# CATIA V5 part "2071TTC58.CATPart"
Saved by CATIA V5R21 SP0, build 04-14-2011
Part number: 2071TTC58
Bounding box of the stored display mesh (mm): x -10 to 10, y 0 to 1000, z -19.5 to 16.5
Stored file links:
  C:\Users\ALI OZGUN\Desktop\alhan\PROFILLER\2071TTC58.CATPart
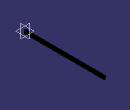
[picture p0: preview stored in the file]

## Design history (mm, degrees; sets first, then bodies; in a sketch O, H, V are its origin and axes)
Body1 (main body)
  Sketch1 on zx-plane, origin (0, 0, 0), H (-1, 0, 0), V (0, 0, 1)
    line L1 (10, 13.9) -> (10, -16.5)
    line L2 (10, -16.5) -> (-10, -16.5)
    line L3 (-10, -16.5) -> (-10, -3.2)
    line L4 (-10, 16.5) -> (-0.8, 16.5)
    point P4 (-10, 2)
    line L5 (-0.8, -3.2) -> (-10, -3.2)
    line L6 (-10, 7.2) -> (-0.8, 7.2)
    point P5 (-9.0936, 12.527)
    point P6 (2, 2)
    line L7 (4.8, 9.75) -> (4.8, -5.75)
    line L8 (4.8, -5.75) -> (-0.8, -5.75)
    line L9 (-0.8, -5.75) -> (-0.8, -3.2)
    line L10 (-0.8, 9.75) -> (4.8, 9.75)
    line L11 (10, 13.9) -> (-0.8, 13.9)
    line L12 (-0.8, 13.9) -> (-0.8, 16.5)
    axis line L13 (-44.5224, 2) -> (23.1973, 2)
    line L14 (-10, 7.2) -> (-10, 16.5)
    point P18 (-0.8, 7.2)
    line L15 (-0.8, 7.2) -> (-0.8, 9.75)
    distance L6 L5 = 10.4
    distance L10 L8 = 15.5
    distance L7 L9 = 5.6
    distance L12 L3 = 9.2
    distance L1 L3 = 20
    distance L4 L2 = 33
    distance L13 L2 = 18.5
    distance L11 L4 = 2.6
    vertical: L1 V, L3 V, L7 V, L9 V, L12 V, L14 V, L15 V
    horizontal: L2 H, L4 H, L5 H, L6 H, L8 H, L10 H, L11 H, L13 H
    equidistance: L1 L3 O, L2 L4 O, L5 L6 P4, L7 L9 P6, L8 L10 P6
    coincidence: P4 L3, L9 L12, L3 L14, L9 P18, L9 L15
    symmetry: L6 L5 L13, L8 L10 L13
  Pad1: profile Sketch1, direction (0, 1, 0), length 1000
  Body2
    Solid1: linked copy from another document
  Remove1: tool Body2
  RemoveFace1: RemoveFaces (face of Solid1; face of Solid1)
Body3
  Sketch2 on start face of Pad1, origin (0, 0, 0), H (1, 0, 0), V (0, 0, 1)
    point P1 (0, -11.1417)
    line L1 (10, -10.5) -> (10, -18.5)
    line L2 (9, -19.5) -> (-9, -19.5)
    line L3 (-10, -18.5) -> (-10, -10.5)
    line L4 (9, -9.5) -> (5, -9.5)
    point P2 (5, -9.5)
    line L5 (-9, -9.5) -> (-5, -9.5)
    point P3 (-5, -9.5)
    reference projected line E1 (0.8, 16.5) -> (10, 16.5) from edge [start face of Pad1 | face of Pad1 from Sketch1.L4]
    arc A1 centre (9, -10.5) radius 1 from (10, -10.5) to (9, -9.5) ccw
    arc A2 centre (9, -18.5) radius 1 from (10, -18.5) to (9, -19.5) cw
    arc A3 centre (-9, -18.5) radius 1 from (-9, -19.5) to (-10, -18.5) cw
    arc A4 centre (-9, -10.5) radius 1 from (-10, -10.5) to (-9, -9.5) cw
    distance P2 P3 = 10
    distance L2 E1 = 36
    distance L1 L3 = 20
    distance L4 L2 = 10
    radius A1 = 1
    radius A2 = 1 {= Sketch2.radius(A1)}
    radius A3 = 1 {= Sketch2.radius(A1)}
    radius A4 = 1 {= Sketch2.radius(A1)}
    coincidence: P1 V
    vertical: L1 V, L3 V
    horizontal: L2 H, L4 H, L5 H
    equidistance: L1 L3 P1
    symmetry: P2 P3 V
    tangency: A1 L1, A1 L4, A2 L1, A2 L2, A3 L2, A3 L3, A4 L3, A4 L5
  Pad2: profile Sketch2, direction (0, 1, 0), length 1000, thin wall 1.5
